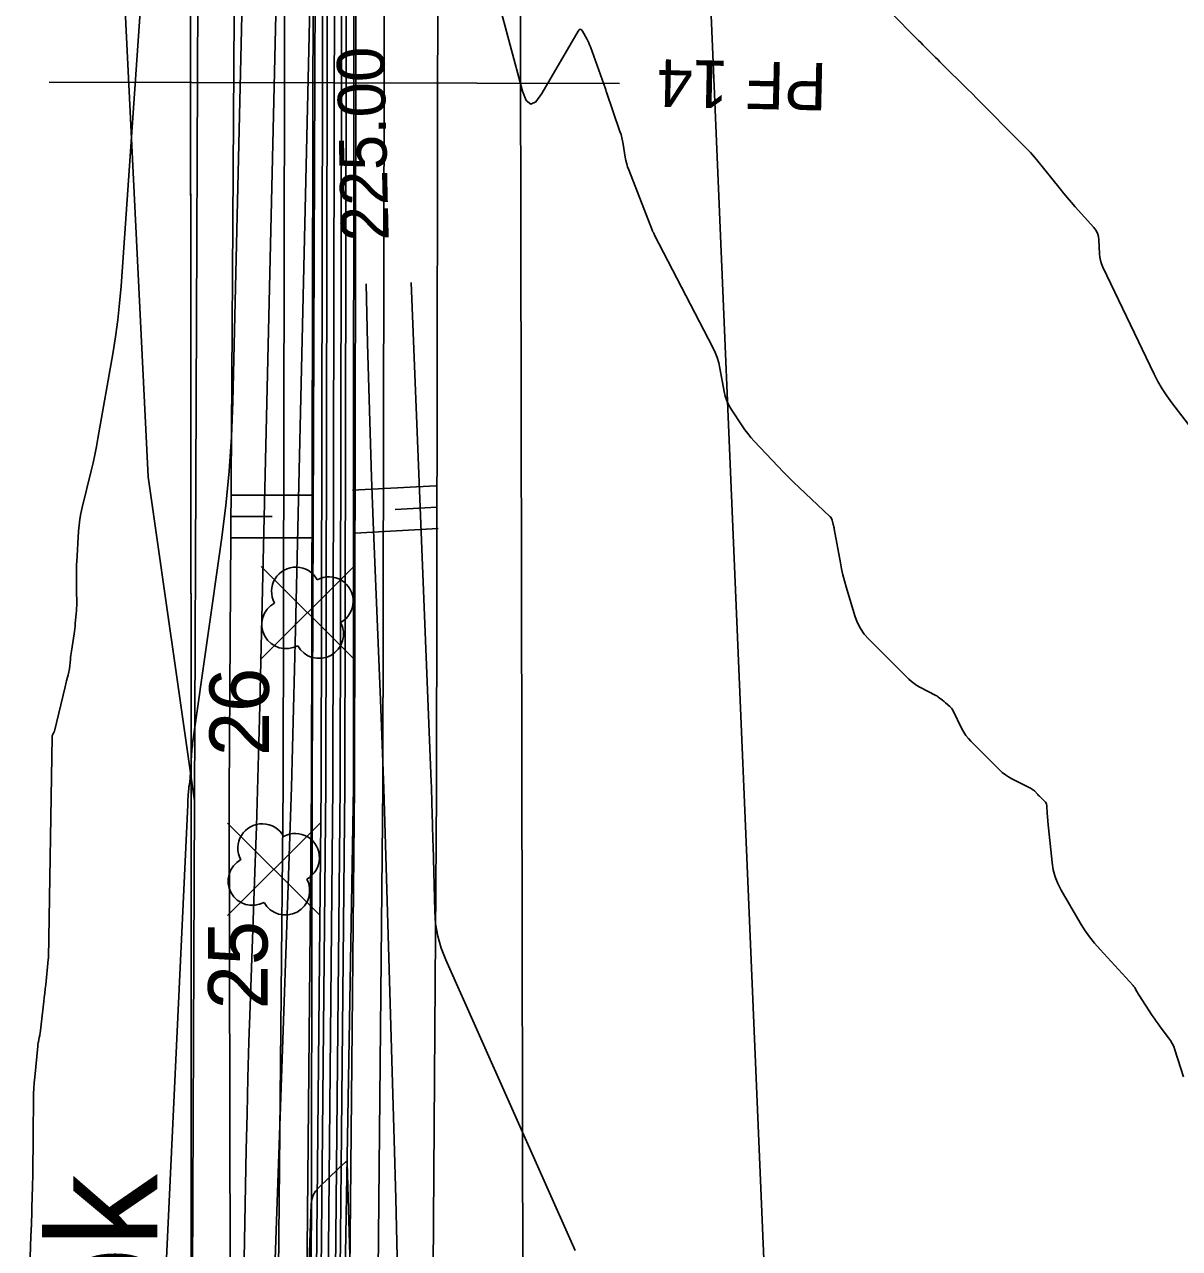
# Model space of a CAD drawing. Extents: x -534410 to -534262, y -1190162 to -1189584.
# Drawn here: x -534372.95 to -534348.66, y -1189830.22 to -1189804.46 of the extents above; entities that cross this region are included whole.
import ezdxf

# ---------------------------------------------------------------- set-up
doc = ezdxf.new("R2010")
doc.units = 0
for name, color, linetype in [('30', 7, 'Continuous'), ('31', 7, 'Continuous'), ('40', 7, 'Continuous'), ('_linie', 7, 'Continuous'), ('_N_osa', 7, 'Continuous'), ('_N_tenká', 7, 'Continuous'), ('_N_tenká_velmi', 7, 'Continuous'), ('_N_text', 7, 'Continuous'), ('_přístup', 7, 'Continuous'), ('_tenka', 7, 'Continuous'), ('_velmi_tenka', 7, 'Continuous'), ('Default', 7, 'Continuous'), ('Hranice parcel', 7, 'Continuous'), ('Pop  PČ popisy', 7, 'Continuous')]:
    doc.layers.add(name, color=color, linetype=linetype)

msp = doc.modelspace()

# ---------------------------------------------------------------- linework, layer by layer
at = {"layer": '30'}
for points in [[(-534370.569, -1189843.242), (-534369.518, -1189820.88), (-534369.518, -1189820.872), (-534369.517, -1189820.856), (-534369.517, -1189820.836), (-534369.516, -1189820.816), (-534369.516, -1189820.799), (-534369.515, -1189820.777), (-534369.515, -1189820.744), (-534369.514, -1189820.737), (-534369.51, -1189820.699), (-534369.509, -1189820.687), (-534369.509, -1189820.685), (-534369.507, -1189820.597), (-534369.506, -1189820.595), (-534369.501, -1189820.574), (-534369.5, -1189820.569), (-534369.499, -1189820.562), (-534369.498, -1189820.55), (-534369.497, -1189820.542), (-534369.497, -1189820.525), (-534369.496, -1189820.51), (-534369.495, -1189820.503), (-534369.49, -1189820.484), (-534369.488, -1189820.474), (-534369.482, -1189820.439), (-534369.481, -1189820.432), (-534369.48, -1189820.425), (-534369.479, -1189820.418), (-534369.479, -1189820.411), (-534369.457, -1189820.094), (-534369.447, -1189819.956), (-534369.431, -1189819.725), (-534369.427, -1189819.679), (-534369.423, -1189819.633), (-534369.418, -1189819.587), (-534369.412, -1189819.541), (-534368.811, -1189815.306), (-534368.719, -1189814.585), (-534368.649, -1189813.861), (-534368.6, -1189813.136), (-534368.572, -1189812.408), (-534367.974, -1189786.766)], [(-534367.679, -1189830.441), (-534367.447, -1189823.822), (-534367.391, -1189822.167), (-534367.34, -1189820.512), (-534367.294, -1189818.856), (-534367.253, -1189817.201), (-534366.829, -1189798.889), (-534366.819, -1189798.744), (-534366.799, -1189798.695), (-534366.77, -1189798.739), (-534366.73, -1189798.878), (-534366.506, -1189799.806), (-534366.479, -1189799.878), (-534366.444, -1189799.907), (-534366.402, -1189799.892), (-534366.351, -1189799.834), (-534366.134, -1189799.511), (-534366.086, -1189799.452), (-534366.051, -1189799.438), (-534366.029, -1189799.469), (-534366.02, -1189799.544), (-534365.914, -1189803.919)], [(-534363.773, -1189801.02), (-534362.475, -1189805.863), (-534362.398, -1189806.061), (-534362.304, -1189806.136), (-534362.194, -1189806.088), (-534362.068, -1189805.917), (-534361.308, -1189804.604), (-534361.285, -1189804.574), (-534361.262, -1189804.564), (-534361.239, -1189804.574), (-534361.216, -1189804.604), (-534361.126, -1189804.764), (-534361.104, -1189804.805), (-534361.084, -1189804.846), (-534361.066, -1189804.888), (-534361.049, -1189804.931), (-534360.731, -1189805.817), (-534360.725, -1189805.835), (-534360.714, -1189805.87), (-534360.708, -1189805.887), (-534360.427, -1189806.713), (-534360.405, -1189806.779), (-534360.387, -1189806.846), (-534360.372, -1189806.914), (-534360.359, -1189806.982), (-534360.315, -1189807.257), (-534360.302, -1189807.325), (-534360.286, -1189807.392), (-534360.266, -1189807.458), (-534360.242, -1189807.524), (-534359.746, -1189808.806), (-534359.745, -1189808.811), (-534359.742, -1189808.815), (-534359.74, -1189808.819), (-534359.737, -1189808.823), (-534359.725, -1189808.837), (-534359.723, -1189808.841), (-534359.72, -1189808.845), (-534359.718, -1189808.849), (-534359.716, -1189808.853), (-534359.707, -1189808.874), (-534359.703, -1189808.884), (-534359.698, -1189808.894), (-534358.473, -1189811.259), (-534358.423, -1189811.364), (-534358.382, -1189811.472), (-534358.349, -1189811.583), (-534358.324, -1189811.697), (-534358.236, -1189812.185), (-534358.213, -1189812.284), (-534358.18, -1189812.38), (-534358.138, -1189812.472), (-534358.085, -1189812.56), (-534357.857, -1189812.905), (-534357.798, -1189812.99), (-534357.736, -1189813.072), (-534357.671, -1189813.151), (-534357.602, -1189813.228), (-534357.102, -1189813.762), (-534356.994, -1189813.875), (-534356.885, -1189813.986), (-534356.773, -1189814.096), (-534356.66, -1189814.204), (-534356.01, -1189814.812), (-534355.994, -1189814.829), (-534355.981, -1189814.848), (-534355.971, -1189814.868), (-534355.964, -1189814.891), (-534355.939, -1189814.983), (-534355.934, -1189815.006), (-534355.928, -1189815.029), (-534355.923, -1189815.052), (-534355.919, -1189815.076), (-534355.789, -1189815.792), (-534355.764, -1189815.919), (-534355.736, -1189816.045), (-534355.704, -1189816.17), (-534355.669, -1189816.295), (-534355.486, -1189816.902), (-534355.435, -1189817.04), (-534355.369, -1189817.169), (-534355.287, -1189817.288), (-534355.19, -1189817.398), (-534354.347, -1189818.241), (-534354.295, -1189818.289), (-534354.24, -1189818.332), (-534354.182, -1189818.371), (-534354.121, -1189818.406), (-534353.782, -1189818.581), (-534353.763, -1189818.591), (-534353.744, -1189818.603), (-534353.727, -1189818.615), (-534353.71, -1189818.628), (-534353.643, -1189818.683), (-534353.626, -1189818.697), (-534353.609, -1189818.711), (-534353.593, -1189818.725), (-534353.576, -1189818.739), (-534353.49, -1189818.811), (-534353.472, -1189818.829), (-534353.455, -1189818.848), (-534353.44, -1189818.869), (-534353.428, -1189818.891), (-534353.232, -1189819.283), (-534353.192, -1189819.354), (-534353.148, -1189819.421), (-534353.098, -1189819.485), (-534353.043, -1189819.545), (-534352.443, -1189820.144), (-534352.384, -1189820.199), (-534352.32, -1189820.249), (-534352.253, -1189820.294), (-534352.182, -1189820.333), (-534351.789, -1189820.529), (-534351.767, -1189820.542), (-534351.746, -1189820.556), (-534351.726, -1189820.572), (-534351.708, -1189820.59), (-534351.637, -1189820.665), (-534351.619, -1189820.684), (-534351.601, -1189820.702), (-534351.582, -1189820.72), (-534351.564, -1189820.738), (-534351.488, -1189820.809), (-534351.472, -1189820.828), (-534351.459, -1189820.849), (-534351.451, -1189820.871), (-534351.448, -1189820.896), (-534351.438, -1189821.077), (-534351.436, -1189821.115), (-534351.433, -1189821.154), (-534351.429, -1189821.192), (-534351.426, -1189821.231), (-534351.336, -1189822.093), (-534351.312, -1189822.246), (-534351.272, -1189822.395), (-534351.217, -1189822.539), (-534351.145, -1189822.677), (-534350.745, -1189823.362), (-534350.652, -1189823.512), (-534350.551, -1189823.656), (-534350.442, -1189823.795), (-534350.326, -1189823.928), (-534349.634, -1189824.681), (-534349.621, -1189824.696), (-534349.61, -1189824.711), (-534349.599, -1189824.727), (-534349.59, -1189824.743), (-534349.553, -1189824.811), (-534349.543, -1189824.828), (-534349.534, -1189824.844), (-534349.524, -1189824.861), (-534349.513, -1189824.877), (-534349.232, -1189825.312), (-534349.192, -1189825.373), (-534349.15, -1189825.433), (-534349.108, -1189825.492), (-534349.064, -1189825.551), (-534348.886, -1189825.783), (-534348.845, -1189825.842), (-534348.808, -1189825.905), (-534348.778, -1189825.97), (-534348.753, -1189826.038), (-534348.571, -1189826.608)], [(-534365.768, -1189809.917), (-534365.737, -1189811.175), (-534365.712, -1189812.112), (-534365.684, -1189813.05), (-534365.652, -1189813.987), (-534365.616, -1189814.925), (-534365.465, -1189818.673), (-534365.429, -1189819.611), (-534365.395, -1189820.548), (-534365.365, -1189821.485), (-534365.337, -1189822.423), (-534365.18, -1189827.933), (-534365.145, -1189829.164), (-534365.111, -1189830.395)]]:
    msp.add_lwpolyline(points, dxfattribs=at)
at = {"layer": '31'}
for points in [[(-534368.595, -1189844.62), (-534368.288, -1189828.137), (-534368.272, -1189827.381), (-534368.254, -1189826.626), (-534368.232, -1189825.87), (-534368.207, -1189825.115), (-534368.101, -1189822.093), (-534368.075, -1189821.337), (-534368.052, -1189820.581), (-534368.031, -1189819.826), (-534368.012, -1189819.07), (-534367.528, -1189798.201), (-534367.485, -1189796.321), (-534367.441, -1189794.441), (-534367.397, -1189792.561), (-534367.353, -1189790.681), (-534367.147, -1189781.836), (-534367.116, -1189780.619), (-534367.081, -1189779.401), (-534367.07, -1189779.047)], [(-534372.841, -1189830.625), (-534372.82, -1189829.956), (-534372.819, -1189829.938), (-534372.818, -1189829.92), (-534372.818, -1189829.902), (-534372.817, -1189829.884), (-534372.813, -1189829.813), (-534372.812, -1189829.795), (-534372.811, -1189829.777), (-534372.81, -1189829.759), (-534372.81, -1189829.741), (-534372.79, -1189829.078), (-534372.787, -1189828.961), (-534372.784, -1189828.844), (-534372.782, -1189828.728), (-534372.78, -1189828.611), (-534372.773, -1189827.888), (-534372.772, -1189827.86), (-534372.771, -1189827.816), (-534372.771, -1189827.802), (-534372.764, -1189827.078), (-534372.761, -1189826.961), (-534372.756, -1189826.845), (-534372.749, -1189826.729), (-534372.739, -1189826.612), (-534372.676, -1189825.962), (-534372.674, -1189825.939), (-534372.67, -1189825.916), (-534372.666, -1189825.893), (-534372.662, -1189825.871), (-534372.642, -1189825.78), (-534372.638, -1189825.757), (-534372.634, -1189825.734), (-534372.63, -1189825.711), (-534372.627, -1189825.688), (-534372.547, -1189825.022), (-534372.537, -1189824.933), (-534372.527, -1189824.844), (-534372.517, -1189824.756), (-534372.508, -1189824.667), (-534372.455, -1189824.138), (-534372.454, -1189824.131), (-534372.451, -1189824.117), (-534372.45, -1189824.109), (-534372.373, -1189819.451), (-534372.372, -1189819.44), (-534372.37, -1189819.429), (-534372.367, -1189819.419), (-534372.362, -1189819.409), (-534372.341, -1189819.371), (-534372.336, -1189819.361), (-534372.332, -1189819.351), (-534372.329, -1189819.34), (-534372.326, -1189819.33), (-534372.098, -1189818.396), (-534372.091, -1189818.365), (-534372.083, -1189818.334), (-534372.075, -1189818.303), (-534372.067, -1189818.272), (-534372.034, -1189818.148), (-534372.026, -1189818.117), (-534372.02, -1189818.086), (-534372.014, -1189818.054), (-534372.01, -1189818.023), (-534371.989, -1189817.823), (-534371.984, -1189817.779), (-534371.979, -1189817.735), (-534371.973, -1189817.691), (-534371.966, -1189817.648), (-534371.912, -1189817.287), (-534371.905, -1189817.233), (-534371.898, -1189817.179), (-534371.891, -1189817.125), (-534371.886, -1189817.07), (-534371.864, -1189816.853), (-534371.86, -1189816.799), (-534371.857, -1189816.744), (-534371.855, -1189816.69), (-534371.855, -1189816.635), (-534371.857, -1189816.371), (-534371.857, -1189816.321), (-534371.858, -1189816.271), (-534371.858, -1189816.221), (-534371.859, -1189816.171), (-534371.861, -1189815.971), (-534371.861, -1189815.921), (-534371.861, -1189815.871), (-534371.859, -1189815.821), (-534371.856, -1189815.771), (-534371.815, -1189815.121), (-534371.805, -1189814.996), (-534371.789, -1189814.873), (-534371.767, -1189814.75), (-534371.74, -1189814.628), (-534371.551, -1189813.856), (-534371.511, -1189813.686), (-534371.474, -1189813.516), (-534371.44, -1189813.345), (-534371.408, -1189813.174), (-534371.096, -1189811.391), (-534371.039, -1189811.036), (-534370.99, -1189810.68), (-534370.952, -1189810.323), (-534370.922, -1189809.965), (-534369.649, -1189791.643)], [(-534354.713, -1189804.225), (-534354.19, -1189804.755), (-534354.145, -1189804.8), (-534354.101, -1189804.844), (-534354.056, -1189804.889), (-534354.011, -1189804.934), (-534353.833, -1189805.113), (-534353.788, -1189805.158), (-534353.743, -1189805.202), (-534353.698, -1189805.247), (-534353.653, -1189805.291), (-534353.124, -1189805.815), (-534353.021, -1189805.917), (-534352.918, -1189806.019), (-534352.816, -1189806.122), (-534352.713, -1189806.225), (-534352.19, -1189806.754), (-534352.146, -1189806.799), (-534352.101, -1189806.844), (-534352.056, -1189806.889), (-534352.012, -1189806.934), (-534351.833, -1189807.113), (-534351.789, -1189807.158), (-534351.746, -1189807.205), (-534351.704, -1189807.253), (-534351.664, -1189807.301), (-534351.166, -1189807.923), (-534351.089, -1189808.019), (-534351.011, -1189808.113), (-534350.931, -1189808.206), (-534350.85, -1189808.297), (-534350.457, -1189808.735), (-534350.413, -1189808.792), (-534350.381, -1189808.854), (-534350.361, -1189808.92), (-534350.352, -1189808.992), (-534350.338, -1189809.286), (-534350.331, -1189809.358), (-534350.317, -1189809.429), (-534350.296, -1189809.498), (-534350.268, -1189809.566), (-534349.192, -1189811.818), (-534349.111, -1189811.976), (-534349.022, -1189812.129), (-534348.925, -1189812.278), (-534348.82, -1189812.421), (-534348.256, -1189813.15)], [(-534364.821, -1189809.894), (-534364.399, -1189820.399), (-534364.395, -1189820.511), (-534364.391, -1189820.623), (-534364.387, -1189820.734), (-534364.384, -1189820.846), (-534364.371, -1189821.294), (-534364.368, -1189821.406), (-534364.365, -1189821.518), (-534364.362, -1189821.63), (-534364.359, -1189821.742), (-534364.324, -1189823.12), (-534364.305, -1189823.384), (-534364.26, -1189823.643), (-534364.189, -1189823.896), (-534364.093, -1189824.142), (-534361.369, -1189830.256)], [(-534365.907, -1189837.418), (-534366.164, -1189828.418), (-534366.166, -1189828.399), (-534366.174, -1189828.389), (-534366.185, -1189828.39), (-534366.201, -1189828.402), (-534366.274, -1189828.467), (-534366.292, -1189828.483), (-534366.31, -1189828.5), (-534366.328, -1189828.516), (-534366.346, -1189828.533), (-534366.765, -1189828.932), (-534366.832, -1189829.008), (-534366.88, -1189829.093), (-534366.911, -1189829.185), (-534366.924, -1189829.286), (-534367.277, -1189839.352)]]:
    msp.add_lwpolyline(points, dxfattribs=at)
at = {"layer": '_linie'}
for points in [[(-534366.12, -1189620.81), (-534364.52, -1189627.2), (-534365.69, -1189653.8), (-534366.76, -1189684.81), (-534368.14, -1189748.73), (-534368.38, -1189779.14), (-534368.65, -1189820.64), (-534368.59, -1189847.58), (-534367.2, -1189913.8)], [(-534363.12, -1189621.02), (-534362.79, -1189621.58), (-534361.82, -1189627.79), (-534363.46, -1189653.55), (-534365.47, -1189684.77), (-534366.65, -1189748.83), (-534366.75, -1189779.47), (-534366.9, -1189820.47), (-534366.95, -1189846.72), (-534366.338, -1189888.804), (-534363.85, -1189911.95), (-534357.07, -1189929.19), (-534352.334, -1189940.856)], [(-534359.03, -1189621.26), (-534359.41, -1189621.83), (-534360.84, -1189627.76), (-534362.92, -1189653.56), (-534364.64, -1189685), (-534365.94, -1189748.9), (-534366.02, -1189779.52), (-534366.03, -1189820.5), (-534366.48, -1189846.73), (-534365.511, -1189888.873), (-534362.72, -1189912.12), (-534356.62, -1189928.64), (-534351.589, -1189940.594)]]:
    msp.add_lwpolyline(points, dxfattribs=at)
at = {"layer": '_N_osa'}
msp.add_lwpolyline([(-534351.95, -1189940.722), (-534356.845, -1189928.915), (-534363.285, -1189912.035), (-534365.925, -1189888.838), (-534366.715, -1189846.725), (-534366.465, -1189820.485), (-534366.385, -1189779.495), (-534366.295, -1189748.865), (-534365.055, -1189684.885), (-534363.19, -1189653.555), (-534361.333, -1189627.822)], dxfattribs=at)
at = {"layer": '_N_tenká'}
for points in [[(-534352.92, -1189941.124), (-534357.821, -1189929.303), (-534364.313, -1189912.285), (-534366.973, -1189888.908), (-534367.765, -1189846.73), (-534367.515, -1189820.479), (-534367.435, -1189779.492), (-534367.345, -1189748.853), (-534366.104, -1189684.844), (-534364.238, -1189653.486), (-534362.424, -1189628.352), (-534361.782, -1189627.792)], [(-534350.98, -1189940.319), (-534355.869, -1189928.527), (-534362.257, -1189911.785), (-534364.876, -1189888.769), (-534365.665, -1189846.72), (-534365.415, -1189820.491), (-534365.335, -1189779.498), (-534365.245, -1189748.877), (-534364.006, -1189684.926), (-534362.142, -1189653.624), (-534360.329, -1189628.488), (-534360.884, -1189627.851)]]:
    msp.add_lwpolyline(points, dxfattribs=at)
at = {"layer": '_N_tenká_velmi'}
for points in [[(-534352.366, -1189940.894), (-534357.263, -1189929.081), (-534363.726, -1189912.142), (-534366.374, -1189888.868), (-534367.165, -1189846.727), (-534366.915, -1189820.482), (-534366.835, -1189779.494), (-534366.745, -1189748.86), (-534365.505, -1189684.867), (-534363.639, -1189653.525), (-534361.782, -1189627.792)], [(-534352.181, -1189940.817), (-534357.077, -1189929.007), (-534363.53, -1189912.095), (-534366.174, -1189888.855), (-534366.965, -1189846.726), (-534366.715, -1189820.484), (-534366.635, -1189779.494), (-534366.545, -1189748.862), (-534365.305, -1189684.875), (-534363.439, -1189653.539), (-534361.583, -1189627.805)], [(-534352.089, -1189940.779), (-534356.984, -1189928.97), (-534363.432, -1189912.071), (-534366.074, -1189888.848), (-534366.865, -1189846.726), (-534366.615, -1189820.484), (-534366.535, -1189779.495), (-534366.445, -1189748.863), (-534365.205, -1189684.879), (-534363.34, -1189653.545), (-534361.483, -1189627.812)], [(-534351.812, -1189940.664), (-534356.706, -1189928.86), (-534363.138, -1189911.999), (-534365.775, -1189888.828), (-534366.565, -1189846.724), (-534366.315, -1189820.486), (-534366.235, -1189779.495), (-534366.145, -1189748.867), (-534364.905, -1189684.891), (-534363.04, -1189653.565), (-534361.184, -1189627.831)], [(-534351.719, -1189940.626), (-534356.613, -1189928.823), (-534363.04, -1189911.975), (-534365.675, -1189888.822), (-534366.465, -1189846.724), (-534366.215, -1189820.486), (-534366.135, -1189779.496), (-534366.045, -1189748.868), (-534364.805, -1189684.895), (-534362.941, -1189653.571), (-534361.084, -1189627.838)], [(-534351.534, -1189940.549), (-534356.427, -1189928.749), (-534362.844, -1189911.928), (-534365.475, -1189888.808), (-534366.265, -1189846.723), (-534366.015, -1189820.488), (-534365.935, -1189779.496), (-534365.845, -1189748.87), (-534364.605, -1189684.903), (-534362.741, -1189653.585), (-534360.884, -1189627.851)]]:
    msp.add_lwpolyline(points, dxfattribs=at)
at = {"layer": '_N_text'}
msp.add_lwpolyline([(-534360.436, -1189805.703), (-534372.436, -1189805.676)], dxfattribs=at)
at = {"layer": '_přístup'}
for p, q in [((-534366.027, -1189817.813), (-534367.973, -1189815.867)), ((-534367.973, -1189817.813), (-534366.027, -1189815.867)), ((-534366.737, -1189823.213), (-534368.683, -1189821.267)), ((-534368.683, -1189823.213), (-534366.737, -1189821.267))]:
    msp.add_line(p, q, dxfattribs=at)
for centre in [(-534367, -1189816.84), (-534367.71, -1189822.24)]:
    msp.add_circle(centre, 0.000512, dxfattribs=at)
for centre, start, end in [((-534367.245, -1189816.391), 28.6209, 208.6209), ((-534366.551, -1189816.595), 298.6209, 118.6209), ((-534367.449, -1189817.085), 118.6209, 298.6209), ((-534366.755, -1189817.289), 208.6209, 28.6209), ((-534367.955, -1189821.791), 28.6209, 208.6209), ((-534367.261, -1189821.995), 298.6209, 118.6209), ((-534368.159, -1189822.485), 118.6209, 298.6209), ((-534367.465, -1189822.689), 208.6209, 28.6209)]:
    msp.add_arc(centre, 0.512, start, end, dxfattribs=at)
at = {"layer": '_tenka'}
for points in [[(-534349.13, -1189939.73), (-534354.63, -1189926.96), (-534362.03, -1189907.65), (-534364.521, -1189888.74), (-534364.47, -1189846.64), (-534364.29, -1189820.63), (-534364.22, -1189780.69), (-534363.18, -1189749.38), (-534362.5, -1189685.39), (-534360.27, -1189651.6), (-534357.03, -1189627.34), (-534354.77, -1189620.37)], [(-534366.12, -1189620.81), (-534364.52, -1189627.2), (-534365.69, -1189653.8), (-534366.76, -1189684.81), (-534368.14, -1189748.73), (-534368.38, -1189779.14), (-534368.65, -1189820.64), (-534368.59, -1189847.58), (-534367.2, -1189913.8)], [(-534366.12, -1189620.81), (-534364.52, -1189627.2), (-534365.69, -1189653.8), (-534366.76, -1189684.81), (-534368.14, -1189748.73), (-534368.38, -1189779.14), (-534368.65, -1189820.64), (-534368.59, -1189847.58), (-534367.2, -1189913.8)], [(-534363.12, -1189621.02), (-534362.79, -1189621.58), (-534361.82, -1189627.79), (-534363.46, -1189653.55), (-534365.47, -1189684.77), (-534366.65, -1189748.83), (-534366.75, -1189779.47), (-534366.9, -1189820.47), (-534366.95, -1189846.72), (-534366.338, -1189888.804), (-534363.85, -1189911.95), (-534357.07, -1189929.19), (-534352.334, -1189940.856)], [(-534363.12, -1189621.02), (-534362.79, -1189621.58), (-534361.82, -1189627.79), (-534363.46, -1189653.55), (-534365.47, -1189684.77), (-534366.65, -1189748.83), (-534366.75, -1189779.47), (-534366.9, -1189820.47), (-534366.95, -1189846.72), (-534366.338, -1189888.804), (-534363.85, -1189911.95), (-534357.07, -1189929.19), (-534352.334, -1189940.856)], [(-534359.03, -1189621.26), (-534359.41, -1189621.83), (-534360.84, -1189627.76), (-534362.92, -1189653.56), (-534364.64, -1189685), (-534365.94, -1189748.9), (-534366.02, -1189779.52), (-534366.03, -1189820.5), (-534366.48, -1189846.73), (-534365.511, -1189888.873), (-534362.72, -1189912.12), (-534356.62, -1189928.64), (-534351.589, -1189940.594)], [(-534359.03, -1189621.26), (-534359.41, -1189621.83), (-534360.84, -1189627.76), (-534362.92, -1189653.56), (-534364.64, -1189685), (-534365.94, -1189748.9), (-534366.02, -1189779.52), (-534366.03, -1189820.5), (-534366.48, -1189846.73), (-534365.511, -1189888.873), (-534362.72, -1189912.12), (-534356.62, -1189928.64), (-534351.589, -1189940.594)], [(-534368.65, -1189626.81), (-534368.65, -1189626.81), (-534367.31, -1189654.04), (-534367.67, -1189685.23), (-534369.56, -1189748.93), (-534369.48, -1189778.6), (-534369.45, -1189820.62), (-534369.45, -1189847.87), (-534371.206, -1189896.071), (-534372.39, -1189914.47)]]:
    msp.add_lwpolyline(points, dxfattribs=at)
at = {"layer": '_velmi_tenka'}
for p, q in [((-534368.612, -1189814.367), (-534366.879, -1189814.367)), ((-534364.304, -1189814.167), (-534366.053, -1189814.264)), ((-534364.279, -1189814.616), (-534365.154, -1189814.665)), ((-534368.612, -1189814.817), (-534367.746, -1189814.817)), ((-534364.255, -1189815.066), (-534366.004, -1189815.163)), ((-534368.612, -1189815.267), (-534366.879, -1189815.267))]:
    msp.add_line(p, q, dxfattribs=at)
at = {"layer": 'Default'}
for p, q in [((-534369.48, -1189778.6), (-534369.45, -1189820.62)), ((-534369.45, -1189820.62), (-534369.45, -1189847.87))]:
    msp.add_line(p, q, dxfattribs=at)
msp.add_lwpolyline([(-534349.13, -1189939.73), (-534354.63, -1189926.96), (-534362.03, -1189907.65), (-534364.521, -1189888.74), (-534364.47, -1189846.64), (-534364.29, -1189820.63), (-534364.22, -1189780.69), (-534363.18, -1189749.38), (-534362.5, -1189685.39), (-534360.27, -1189651.6), (-534357.03, -1189627.34), (-534354.77, -1189620.37)], dxfattribs=at)
at = {"layer": 'Hranice parcel'}
for p, q in [((-534369.38, -1189820.8), (-534369.14, -1189764.19)), ((-534369.75, -1189908.47), (-534369.38, -1189820.8))]:
    msp.add_line(p, q, dxfattribs=at)
for points in [[(-534359.48, -1189697.97), (-534362.6, -1189764.35), (-534362.34, -1189901.56)], [(-534359.48, -1189697.97), (-534360.42, -1189747.8), (-534359.17, -1189788.69), (-534356.86, -1189843.2), (-534358.53, -1189915.98)], [(-534369.38, -1189820.8), (-534370.35, -1189813.98), (-534372.65, -1189767.31), (-534373.49, -1189759.21)]]:
    msp.add_lwpolyline(points, dxfattribs=at)

# ---------------------------------------------------------------- texts
at = {"layer": '40'}
msp.add_text('225.00', height=1, rotation=91.3946, dxfattribs=at).set_placement((-534365.29, -1189809.007))
at = {"layer": '_N_text'}
msp.add_text('PF 14', height=1, rotation=178.6938, dxfattribs=at).set_placement((-534356.063, -1189805.275))
at = {"layer": '_přístup'}
for s, p in [('26', (-534367.813, -1189819.857)), ('25', (-534367.841, -1189825.185))]:
    msp.add_text(s, height=1.25, rotation=90, dxfattribs=at).set_placement(p)
at = {"layer": 'Pop  PČ popisy'}
msp.add_text('Starohorský potok', height=2.3, rotation=90, dxfattribs=at).set_placement((-534370.162, -1189853.443))

doc.saveas('drawing.dxf')
